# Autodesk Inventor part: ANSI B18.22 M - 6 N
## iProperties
Comments: To add or edit properties for Autodesk Inventor files, use iProperties.
Created: 2004-08
Part Number: ANSI B18.22 M - 6 N
Vendor: Autodesk Inc.
Document SubType Name: Modeling
Designer: John Blackburn
Material: Default
Description: Plain Washer
Standard: ANSI B18.22 M
Size Designation: 6 N
Alert: To add or edit properties for Autodesk Inventor files, use iProperties.
Control State: 0
Master: False
Checked Out: False
Shininess: 64.0
Length Units: 11269
Angle Units: 11279
Time Units: 11290
Mass Units: 11283
Length Display Precision: 3
Angle Display Precision: 2
Compacted: True
Classification: un/spsc 31161807
Density: 0.0
Volumn: 0.0
Area: 0.0
PropertySet Name: Model Information
Author: John Blackburn
Revision Number: 8
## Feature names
1. Body [Extrusion]
